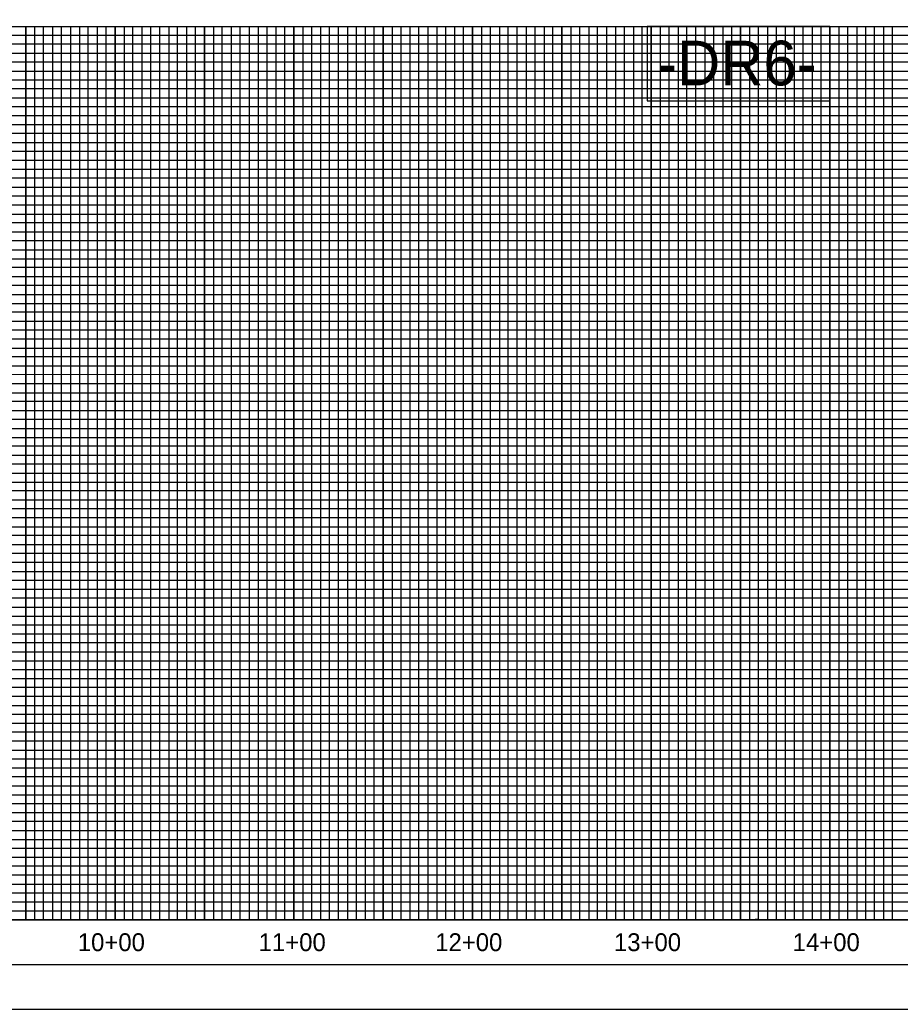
# Model space of a CAD drawing. Extents: x 505602 to 507286, y 483109 to 484209.
# Drawn here: x 506216 to 506708, y 483109 to 483662 of the extents above; entities that cross this region are included whole.
import ezdxf

# ---------------------------------------------------------------- set-up
doc = ezdxf.new("R2010")
doc.units = 0
for name, color, linetype in [('Exist Vertical Profile Vertical Axis Label', 7, 'Continuous'), ('Old_Level_1', 7, 'Continuous'), ('Prop Grid Mask', 7, 'Continuous'), ('Sheet Layout Profile Border Port 2', 7, 'Continuous'), ('Sheet Plot Border Outside CELL', 7, 'Continuous'), ('Sheet Profile CELL', 7, 'Continuous'), ('Sheet Profile Grid Major CELL', 7, 'Continuous'), ('Sheet Profile Grid Middle CELL', 7, 'Continuous'), ('Sheet Profile Grid Minor CELL', 7, 'Continuous')]:
    doc.layers.add(name, color=color, linetype=linetype)

msp = doc.modelspace()

# ---------------------------------------------------------------- linework, layer by layer
at = {"layer": 'Prop Grid Mask'}
msp.add_lwpolyline([(506669.08, 483658.71), (506566.78, 483658.71), (506566.78, 483617), (506669.08, 483617)], close=True, dxfattribs=at)
at = {"layer": 'Sheet Layout Profile Border Port 2'}
msp.add_lwpolyline([(506169.08, 483658.71), (507219.08, 483658.71), (507219.08, 483158.71), (506169.08, 483158.71)], close=True, dxfattribs=at)
at = {"layer": 'Sheet Plot Border Outside CELL'}
msp.add_lwpolyline([(505602.08, 483108.71), (507286.08, 483108.71), (507286.08, 484208.71), (505602.08, 484208.71)], close=True, dxfattribs=at)
at = {"layer": 'Sheet Profile CELL'}
for p, q in [((505769.08, 483658.71), (507269.08, 483658.71)), ((507269.08, 483158.71), (505769.08, 483158.71)), ((505769.08, 483133.71), (507269.08, 483133.71))]:
    msp.add_line(p, q, dxfattribs=at)
msp.add_lwpolyline([(507269.08, 484183.71), (505769.08, 484183.71), (505769.08, 483133.71), (507269.08, 483133.71)], close=True, dxfattribs=at)
at = {"layer": 'Sheet Profile Grid Major CELL'}
for p, q in [((506269.08, 483658.71), (506319.08, 483658.71)), ((506369.08, 483658.71), (506419.08, 483658.71)), ((506469.08, 483658.71), (506519.08, 483658.71))]:
    msp.add_line(p, q, dxfattribs=at)
for points in [[(506169.08, 483658.71), (506219.08, 483658.71), (506219.08, 483158.71), (506269.08, 483158.71), (506269.08, 483658.71), (506319.08, 483658.71), (506319.08, 483158.71), (506369.08, 483158.71), (506369.08, 483658.71), (506419.08, 483658.71), (506419.08, 483158.71), (506469.08, 483158.71), (506469.08, 483658.71), (506519.08, 483658.71), (506519.08, 483158.71), (506569.08, 483158.71), (506569.08, 483658.71), (506619.08, 483658.71), (506619.08, 483158.71), (506669.08, 483158.71), (506669.08, 483658.71), (506719.08, 483658.71)], [(506169.08, 483158.71), (506219.08, 483158.71), (506219.08, 483658.71), (506269.08, 483658.71), (506269.08, 483158.71), (506319.08, 483158.71), (506319.08, 483658.71), (506369.08, 483658.71), (506369.08, 483158.71), (506419.08, 483158.71), (506419.08, 483658.71), (506469.08, 483658.71), (506469.08, 483158.71), (506519.08, 483158.71), (506519.08, 483658.71), (506569.08, 483658.71), (506569.08, 483158.71), (506619.08, 483158.71), (506619.08, 483658.71), (506669.08, 483658.71), (506669.08, 483158.71), (506719.08, 483158.71)], [(507269.08, 483608.71), (505769.08, 483608.71)], [(507269.08, 483558.71), (505769.08, 483558.71), (505769.08, 483508.71), (507269.08, 483508.71)], [(507269.08, 483458.71), (505769.08, 483458.71), (505769.08, 483408.71), (507269.08, 483408.71)], [(507269.08, 483358.71), (505769.08, 483358.71), (505769.08, 483308.71), (507269.08, 483308.71)], [(507269.08, 483258.71), (505769.08, 483258.71), (505769.08, 483258.71), (505769.08, 483208.71), (507269.08, 483208.71)], [(507269.08, 483158.71), (505769.08, 483158.71)]]:
    msp.add_lwpolyline(points, dxfattribs=at)
at = {"layer": 'Sheet Profile Grid Middle CELL'}
for points in [[(506194.08, 483658.71), (506244.08, 483658.71), (506244.08, 483158.71), (506294.08, 483158.71), (506294.08, 483658.71), (506344.08, 483658.71), (506344.08, 483158.71), (506394.08, 483158.71), (506394.08, 483158.71), (506394.08, 483658.71), (506444.08, 483658.71), (506444.08, 483158.71), (506494.08, 483158.71), (506494.08, 483658.71), (506544.08, 483658.71), (506544.08, 483158.71), (506594.08, 483158.71), (506594.08, 483658.71), (506644.08, 483658.71), (506644.08, 483158.71), (506694.08, 483158.71), (506694.08, 483658.71), (506744.08, 483658.71)], [(505769.08, 483633.71), (507269.08, 483633.71)], [(507269.08, 483583.71), (505769.08, 483583.71), (505769.08, 483533.71), (507269.08, 483533.71)], [(507269.08, 483483.71), (505769.08, 483483.71), (505769.08, 483433.71), (507269.08, 483433.71)], [(507269.08, 483383.71), (505769.08, 483383.71), (505769.08, 483333.71), (507269.08, 483333.71)], [(507269.08, 483283.71), (505769.08, 483283.71), (505769.08, 483233.71), (507269.08, 483233.71)], [(507269.08, 483183.71), (505769.08, 483183.71)]]:
    msp.add_lwpolyline(points, dxfattribs=at)
at = {"layer": 'Sheet Profile Grid Minor CELL'}
for p, q in [((505819.08, 483653.71), (507219.08, 483653.71)), ((507219.08, 483648.71), (505819.08, 483648.71)), ((505819.08, 483643.71), (507219.08, 483643.71)), ((507219.08, 483638.71), (505819.08, 483638.71)), ((505819.08, 483628.71), (507219.08, 483628.71)), ((507219.08, 483623.71), (505819.08, 483623.71)), ((505819.08, 483618.71), (507219.08, 483618.71)), ((507219.08, 483613.71), (505819.08, 483613.71)), ((505819.08, 483603.71), (507219.08, 483603.71)), ((507219.08, 483598.71), (505819.08, 483598.71)), ((505819.08, 483593.71), (507219.08, 483593.71)), ((507219.08, 483588.71), (505819.08, 483588.71)), ((505819.08, 483578.71), (507219.08, 483578.71)), ((507219.08, 483573.71), (505819.08, 483573.71)), ((505819.08, 483568.71), (507219.08, 483568.71)), ((507219.08, 483563.71), (505819.08, 483563.71)), ((505819.08, 483553.71), (507219.08, 483553.71)), ((507219.08, 483548.71), (505819.08, 483548.71)), ((505819.08, 483543.71), (507219.08, 483543.71)), ((507219.08, 483538.71), (505819.08, 483538.71)), ((505819.08, 483528.71), (507219.08, 483528.71)), ((507219.08, 483523.71), (505819.08, 483523.71)), ((505819.08, 483518.71), (507219.08, 483518.71)), ((507219.08, 483513.71), (505819.08, 483513.71)), ((505819.08, 483503.71), (507219.08, 483503.71)), ((507219.08, 483498.71), (505819.08, 483498.71)), ((505819.08, 483493.71), (507219.08, 483493.71)), ((507219.08, 483488.71), (505819.08, 483488.71)), ((505819.08, 483478.71), (507219.08, 483478.71)), ((507219.08, 483473.71), (505819.08, 483473.71)), ((505819.08, 483468.71), (507219.08, 483468.71)), ((507219.08, 483463.71), (505819.08, 483463.86)), ((505819.08, 483453.71), (507219.08, 483453.71)), ((507219.08, 483448.71), (505819.08, 483448.71)), ((505819.08, 483443.71), (507219.08, 483443.71)), ((507219.08, 483438.71), (505819.08, 483438.71)), ((505819.08, 483428.71), (507219.08, 483428.71)), ((507219.08, 483423.71), (505819.08, 483423.71)), ((505819.08, 483418.71), (507219.08, 483418.71)), ((507219.08, 483413.71), (505819.08, 483413.71)), ((505819.08, 483403.71), (507219.08, 483403.71)), ((507219.08, 483398.71), (505819.08, 483398.71)), ((505819.08, 483393.71), (507219.08, 483393.71)), ((507219.08, 483388.71), (505819.08, 483388.71)), ((505819.08, 483378.71), (507219.08, 483378.71)), ((507219.08, 483373.71), (505819.08, 483373.71)), ((505819.08, 483368.71), (507219.08, 483368.71)), ((507219.08, 483363.71), (505819.08, 483363.71)), ((505819.08, 483353.71), (507219.08, 483353.71)), ((507219.08, 483348.71), (505819.08, 483348.71)), ((505819.08, 483343.71), (507219.08, 483343.71)), ((507219.08, 483338.71), (505819.08, 483338.71)), ((505819.08, 483328.71), (507219.08, 483328.71)), ((507219.08, 483323.71), (505819.08, 483323.71)), ((505819.08, 483318.71), (507219.08, 483318.71)), ((507219.08, 483313.71), (505819.08, 483313.71)), ((505819.08, 483303.71), (507219.08, 483303.71)), ((507219.08, 483298.71), (505819.08, 483298.71)), ((505819.08, 483293.71), (507219.08, 483293.71)), ((507219.08, 483288.71), (505819.08, 483288.71)), ((505819.08, 483278.71), (507219.08, 483278.71)), ((507219.08, 483273.71), (505819.08, 483273.71)), ((505819.08, 483268.71), (507219.08, 483268.71)), ((507219.08, 483263.71), (505819.08, 483263.71)), ((505819.08, 483253.71), (507219.08, 483253.71)), ((507219.08, 483248.71), (505819.08, 483248.71)), ((505819.08, 483243.71), (507219.08, 483243.71)), ((507219.08, 483238.71), (505819.08, 483238.71)), ((505819.08, 483228.71), (507219.08, 483228.71)), ((507219.08, 483223.71), (505819.08, 483223.71)), ((505819.08, 483218.71), (507219.08, 483218.71)), ((507219.08, 483213.71), (505819.08, 483213.71)), ((505819.08, 483203.71), (507219.08, 483203.71)), ((507219.08, 483198.71), (505819.08, 483198.71)), ((505819.08, 483193.71), (507219.08, 483193.71)), ((507219.08, 483188.71), (505819.08, 483188.71)), ((505819.08, 483178.71), (507219.08, 483178.71)), ((507219.08, 483173.71), (505819.08, 483173.71)), ((505819.08, 483168.71), (507219.08, 483168.71)), ((505819.08, 483163.71), (507219.08, 483163.71))]:
    msp.add_line(p, q, dxfattribs=at)
for points in [[(506214.08, 483658.71), (506224.08, 483658.71), (506224.08, 483158.71), (506229.08, 483158.71), (506229.08, 483658.71), (506234.08, 483658.71), (506234.08, 483158.71), (506239.08, 483158.71), (506239.08, 483658.71), (506249.08, 483658.71), (506249.08, 483158.71), (506254.08, 483158.71), (506254.08, 483658.71), (506259.08, 483658.71), (506259.08, 483158.71), (506264.08, 483158.71), (506264.08, 483658.71), (506274.08, 483658.71), (506274.08, 483158.71), (506279.08, 483158.71), (506279.08, 483658.71), (506284.08, 483658.71), (506284.08, 483158.71), (506289.08, 483158.71), (506289.08, 483658.71), (506299.08, 483658.71), (506299.08, 483158.71), (506304.08, 483158.71), (506304.08, 483658.71), (506309.08, 483658.71), (506309.08, 483158.71), (506314.08, 483158.71), (506314.08, 483658.71), (506324.08, 483658.71), (506324.08, 483158.71), (506329.08, 483158.71), (506329.08, 483658.71), (506334.08, 483658.71), (506334.08, 483158.71), (506339.08, 483158.71), (506339.08, 483658.71), (506349.08, 483658.71)], [(506349.08, 483658.71), (506349.08, 483158.71), (506354.08, 483158.71), (506354.08, 483658.71), (506359.08, 483658.71), (506359.08, 483158.71), (506364.08, 483158.71), (506364.08, 483658.71), (506374.08, 483658.71), (506374.08, 483158.71), (506379.08, 483158.71), (506379.08, 483658.71), (506384.08, 483658.71), (506384.08, 483158.71), (506389.08, 483158.71), (506389.08, 483658.71), (506399.08, 483658.71), (506399.08, 483158.71), (506404.08, 483158.71), (506404.08, 483658.71), (506409.08, 483658.71), (506409.08, 483158.71), (506414.08, 483158.71), (506414.08, 483658.71), (506424.08, 483658.71), (506424.08, 483158.71), (506429.08, 483158.71), (506429.08, 483658.71), (506434.08, 483658.71), (506434.08, 483158.71), (506439.08, 483158.71), (506439.08, 483658.71), (506449.08, 483658.71), (506449.08, 483158.71), (506454.08, 483158.71), (506454.08, 483658.71), (506459.08, 483658.71), (506459.08, 483158.71), (506464.08, 483158.71), (506464.08, 483658.71), (506474.08, 483658.71), (506474.08, 483158.71), (506474.08, 483158.71), (506479.08, 483158.71), (506479.08, 483658.71), (506484.08, 483658.71), (506484.08, 483158.71), (506489.08, 483158.71), (506489.08, 483658.71), (506499.08, 483658.71), (506499.08, 483158.71), (506504.08, 483158.71), (506504.08, 483658.71), (506509.08, 483658.71), (506509.08, 483158.71), (506514.08, 483158.71), (506514.08, 483658.71), (506524.08, 483658.71), (506524.08, 483158.71), (506529.08, 483158.71), (506529.08, 483658.71), (506534.08, 483658.71), (506534.08, 483158.71), (506539.08, 483158.71), (506539.08, 483658.71), (506549.08, 483658.71), (506549.08, 483158.71), (506554.08, 483158.71), (506554.08, 483658.71), (506559.08, 483658.71), (506559.08, 483158.71), (506564.08, 483158.71), (506564.08, 483658.71), (506574.08, 483658.71), (506574.08, 483158.71), (506579.08, 483158.71), (506579.08, 483658.71), (506584.08, 483658.71), (506584.08, 483158.71), (506589.08, 483158.71), (506589.08, 483658.71), (506599.08, 483658.71), (506599.08, 483158.71), (506604.08, 483158.71), (506604.08, 483658.71), (506609.08, 483658.71), (506609.08, 483158.71), (506614.08, 483158.71), (506614.08, 483658.71), (506624.08, 483658.71), (506624.08, 483158.71), (506628.78, 483159.26), (506629.08, 483158.71), (506629.08, 483658.71), (506634.08, 483658.71), (506634.08, 483158.71), (506639.08, 483158.71), (506639.08, 483658.71), (506649.08, 483658.71), (506649.08, 483158.71), (506654.08, 483158.71)], [(506654.08, 483158.71), (506654.08, 483658.71), (506659.08, 483658.71), (506659.08, 483158.71), (506664.08, 483158.71), (506664.08, 483658.71), (506674.08, 483658.71), (506674.08, 483158.71), (506679.08, 483158.71), (506679.08, 483658.71), (506684.08, 483658.71), (506684.08, 483158.71), (506689.08, 483158.71), (506689.08, 483658.71), (506699.08, 483658.71), (506699.08, 483158.71), (506704.08, 483158.71), (506704.08, 483658.71), (506709.08, 483658.71)]]:
    msp.add_lwpolyline(points, dxfattribs=at)

# ---------------------------------------------------------------- texts
at = {"layer": 'Exist Vertical Profile Vertical Axis Label'}
for s, p in [('10+00', (506248.21, 483141.21)), ('11+00', (506349.41, 483141.21)), ('12+00', (506448.21, 483141.21)), ('13+00', (506548.21, 483141.21)), ('14+00', (506648.21, 483141.21))]:
    msp.add_text(s, height=10, dxfattribs=at).set_placement(p)
at = {"layer": 'Old_Level_1'}
msp.add_text('-DR6-', height=25, dxfattribs=at).set_placement((506572.42, 483625.68))

doc.saveas('drawing.dxf')
